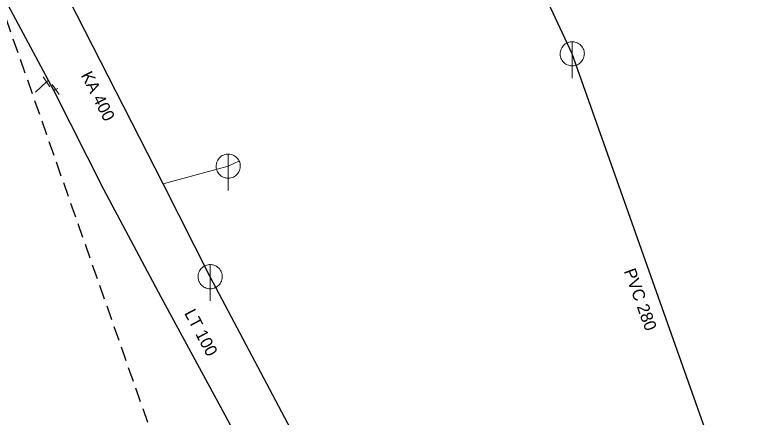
# Model space of a CAD drawing. Extents: x -659250 to -657316, y -997555 to -993684.
# Drawn here: x -658371.5 to -658309.7, y -996007.8 to -995974.5 of the extents above; entities that cross this region are included whole.
import ezdxf

# ---------------------------------------------------------------- set-up
doc = ezdxf.new("R2010")
doc.units = 0
doc.header["$LTSCALE"] = 0.4
doc.linetypes.add('MEDIUM_DASHED', pattern=[4.5, 3, -1.5])
doc.layers.add('1', color=7, linetype='Continuous')
for name, color, linetype, lineweight in [('11', 7, 'Continuous', 13), ('13', 7, 'Continuous', 13), ('14', 7, 'Continuous', 25), ('17', 7, 'Continuous', 25), ('22', 7, 'Continuous', 13), ('34', 7, 'Continuous', 13), ('63', 7, 'MEDIUM_DASHED', 25)]:
    doc.layers.add(name, color=color, linetype=linetype, lineweight=lineweight)

msp = doc.modelspace()

# ---------------------------------------------------------------- linework, layer by layer
at = {"layer": '11'}
for p, q in [((-658352.894, -995986.594), (-658353.818, -995987.028)), ((-658353.818, -995987.028), (-658359.201, -995988.5))]:
    msp.add_line(p, q, dxfattribs=at)
at = {"layer": '13'}
for p, q in [((-658368.848, -995980.055), (-658369.754, -995980.918)), ((-658368.096, -995980.684), (-658367.921, -995980.601))]:
    msp.add_line(p, q, dxfattribs=at)
at = {"layer": '14'}
for p, q in [((-658325.359, -995977.739), (-658339.26, -995947.92)), ((-658310.77, -996018.93), (-658325.359, -995977.739)), ((-658340.107, -996024.908), (-658355.309, -995996.164))]:
    msp.add_line(p, q, dxfattribs=at)
at = {"layer": '14', "lineweight": 13}
for p, q in [((-658368.688, -995979.949), (-658368.848, -995980.055)), ((-658368.234, -995980.783), (-658368.096, -995980.684))]:
    msp.add_line(p, q, dxfattribs=at)
at = {"layer": '14'}
msp.add_lwpolyline([(-658355.309, -995996.164), (-658359.201, -995988.5), (-658367.629, -995971.967), (-658370.486, -995966.386)], dxfattribs=at)
at = {"layer": '17'}
msp.add_lwpolyline([(-658341.335, -996031.25), (-658341.837, -996030.092), (-658343.546, -996026.971), (-658347.557, -996019.669), (-658349.793, -996015.622), (-658354.063, -996007.618), (-658359.368, -995997.851), (-658364.107, -995988.964), (-658368.234, -995980.783), (-658368.688, -995979.949), (-658374.125, -995969.846), (-658379.467, -995959.975), (-658383.866, -995951.561), (-658388.124, -995943.833), (-658392.638, -995935.302), (-658395.929, -995928.816)], dxfattribs=at)
at = {"layer": '22'}
for p, q in [((-658325.359, -995979.739), (-658325.358, -995976.739)), ((-658353.818, -995989.028), (-658353.817, -995986.028)), ((-658355.309, -995998.164), (-658355.308, -995995.164))]:
    msp.add_line(p, q, dxfattribs=at)
for points in [[(-658324.359, -995977.739), (-658324.364, -995977.63), (-658324.382, -995977.522), (-658324.412, -995977.416), (-658324.452, -995977.315), (-658324.504, -995977.218), (-658324.566, -995977.128), (-658324.638, -995977.045), (-658324.718, -995976.971), (-658324.806, -995976.905), (-658324.9, -995976.85), (-658325, -995976.805), (-658325.105, -995976.772), (-658325.212, -995976.75), (-658325.321, -995976.74), (-658325.431, -995976.742), (-658325.539, -995976.756), (-658325.646, -995976.781), (-658325.749, -995976.818), (-658325.847, -995976.867), (-658325.939, -995976.925), (-658326.025, -995976.994), (-658326.102, -995977.071), (-658326.171, -995977.157), (-658326.23, -995977.249), (-658326.278, -995977.347), (-658326.315, -995977.45), (-658326.341, -995977.557), (-658326.355, -995977.665), (-658326.358, -995977.775), (-658326.348, -995977.884), (-658326.327, -995977.991), (-658326.293, -995978.095), (-658326.249, -995978.195), (-658326.194, -995978.29), (-658326.128, -995978.378), (-658326.054, -995978.458), (-658325.971, -995978.53), (-658325.881, -995978.592), (-658325.785, -995978.644), (-658325.683, -995978.685), (-658325.578, -995978.715), (-658325.47, -995978.733), (-658325.36, -995978.739), (-658325.251, -995978.733), (-658325.143, -995978.715), (-658325.038, -995978.686), (-658324.936, -995978.645), (-658324.839, -995978.593), (-658324.749, -995978.531), (-658324.666, -995978.46), (-658324.591, -995978.38), (-658324.526, -995978.292), (-658324.47, -995978.198), (-658324.426, -995978.098), (-658324.392, -995977.994), (-658324.37, -995977.886), (-658324.36, -995977.777)], [(-658352.818, -995987.028), (-658352.823, -995986.919), (-658352.841, -995986.811), (-658352.871, -995986.705), (-658352.911, -995986.604), (-658352.963, -995986.507), (-658353.025, -995986.417), (-658353.097, -995986.334), (-658353.177, -995986.26), (-658353.265, -995986.194), (-658353.359, -995986.139), (-658353.459, -995986.094), (-658353.564, -995986.061), (-658353.671, -995986.039), (-658353.78, -995986.029), (-658353.89, -995986.031), (-658353.998, -995986.045), (-658354.105, -995986.07), (-658354.208, -995986.107), (-658354.306, -995986.156), (-658354.398, -995986.214), (-658354.484, -995986.283), (-658354.561, -995986.36), (-658354.63, -995986.446), (-658354.689, -995986.538), (-658354.737, -995986.636), (-658354.774, -995986.739), (-658354.8, -995986.846), (-658354.814, -995986.954), (-658354.817, -995987.064), (-658354.807, -995987.173), (-658354.786, -995987.28), (-658354.752, -995987.384), (-658354.708, -995987.484), (-658354.653, -995987.579), (-658354.587, -995987.667), (-658354.513, -995987.747), (-658354.43, -995987.819), (-658354.34, -995987.881), (-658354.244, -995987.933), (-658354.142, -995987.974), (-658354.037, -995988.004), (-658353.929, -995988.022), (-658353.819, -995988.028), (-658353.71, -995988.022), (-658353.602, -995988.004), (-658353.497, -995987.975), (-658353.395, -995987.934), (-658353.298, -995987.882), (-658353.208, -995987.82), (-658353.125, -995987.749), (-658353.05, -995987.669), (-658352.985, -995987.581), (-658352.929, -995987.487), (-658352.885, -995987.387), (-658352.851, -995987.283), (-658352.829, -995987.175), (-658352.819, -995987.066)], [(-658354.309, -995996.164), (-658354.314, -995996.055), (-658354.332, -995995.947), (-658354.362, -995995.841), (-658354.402, -995995.74), (-658354.454, -995995.643), (-658354.516, -995995.553), (-658354.588, -995995.47), (-658354.668, -995995.396), (-658354.756, -995995.33), (-658354.85, -995995.275), (-658354.95, -995995.23), (-658355.055, -995995.197), (-658355.162, -995995.175), (-658355.271, -995995.165), (-658355.381, -995995.167), (-658355.489, -995995.181), (-658355.596, -995995.206), (-658355.699, -995995.243), (-658355.797, -995995.292), (-658355.889, -995995.35), (-658355.975, -995995.419), (-658356.052, -995995.496), (-658356.121, -995995.582), (-658356.18, -995995.674), (-658356.228, -995995.772), (-658356.265, -995995.875), (-658356.291, -995995.982), (-658356.305, -995996.09), (-658356.308, -995996.2), (-658356.298, -995996.309), (-658356.277, -995996.416), (-658356.243, -995996.52), (-658356.199, -995996.62), (-658356.144, -995996.715), (-658356.078, -995996.803), (-658356.004, -995996.883), (-658355.921, -995996.955), (-658355.831, -995997.017), (-658355.735, -995997.069), (-658355.633, -995997.11), (-658355.528, -995997.14), (-658355.42, -995997.158), (-658355.31, -995997.164), (-658355.201, -995997.158), (-658355.093, -995997.14), (-658354.988, -995997.111), (-658354.886, -995997.07), (-658354.789, -995997.018), (-658354.699, -995996.956), (-658354.616, -995996.885), (-658354.541, -995996.805), (-658354.476, -995996.717), (-658354.42, -995996.623), (-658354.376, -995996.523), (-658354.342, -995996.419), (-658354.32, -995996.311), (-658354.31, -995996.202)]]:
    msp.add_lwpolyline(points, close=True, dxfattribs=at)
at = {"layer": '34'}
for p, q in [((-658368.571, -995980.471), (-658369.123, -995979.637)), ((-658368.385, -995980.276), (-658367.806, -995981.091))]:
    msp.add_line(p, q, dxfattribs=at)
at = {"layer": '63'}
msp.add_lwpolyline([(-659116.685, -993855.266), (-658551.464, -993848.288), (-658551.464, -993848.288), (-657316.352, -997490.822), (-657316.352, -997490.822), (-657839.705, -997490.822), (-657839.705, -997490.822)], close=True, dxfattribs=at)

# ---------------------------------------------------------------- texts
at = {"layer": '1'}
for s, rotation, p in [('KA 400', 297, (-658366.028, -995979.503)), ('PVC 280 ', 290, (-658321.104, -995995.697)), ('LT 100', 298, (-658357.48, -995999.172))]:
    msp.add_text(s, height=1, rotation=rotation, dxfattribs=at).set_placement(p)

doc.saveas('drawing.dxf')
